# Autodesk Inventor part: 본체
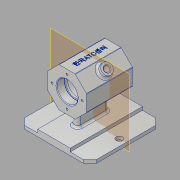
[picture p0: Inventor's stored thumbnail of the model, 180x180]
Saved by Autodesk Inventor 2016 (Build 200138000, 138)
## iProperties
Created: 2018-06
Part Number: 본체
Material: 알루미늄 6061
Document SubType Name: Modeling
Designer: 605-15
Density: 2.7 g/cm^3
Appearance: 알루미늄 - 평지
Mass: 552.644 g
Surface Area: 601.052 cm^2
Volume: 204.683 cm^3
Author: 605-15
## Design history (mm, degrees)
sketch "스케치1"
  geometry: L1 (45, 55)-(-45, 55); L2 (-55, 45)-(-55, -45); L3 (-45, -55)-(45, -55); L4 (55, -45)-(55, 45); L5 (55, 45)-(45, 55); L6 (-45, 55)-(-55, 45); L7 (-55, -45)-(-45, -55); L8 (55, -45)-(45, -55); 7 further points
  constraints: 16 end point, 8 point on line, 2 midpoint, 2 parallel, 2 perpendicular, 1 horizontal, 1 horizontal alignment, 1 vertical alignment
  dimensions: "d0" = 110 distance of point (55, -55) point (55, 55); "d1" = 10 distance of L4.end point (55, 55); "d2" = 10 distance of L1.start point (55, 55) (= d1); "d3" = 10 distance of L1.end point (-55, 55) (= d1); "d4" = 10 distance of L2.start point (-55, 55) (= d3); "d5" = 10 distance of L2.end point (-55, -55) (= d1); "d6" = 10 distance of L3.start point (-55, -55) (= d5); "d7" = 10 distance of L4.start point (55, -55) (= d1); "d8" = 10 distance of L3.end point (55, -55) (= d7)
extrude "돌출1" new body sketch "스케치1" distance "d9" = 5; taper "d10" = 0 deg
sketch "스케치2"
  geometry: L1 (-5, -19)-(-5, 19); L2 (5, 19)-(5, -19); A1 r 5 centre (0, 19) between (5, 19) and (-5, 19); A2 r 5 centre (0, -19) between (-5, -19) and (5, -19); 2 further points
  constraints: 4 end point, 4 point on circle, 4 tangent, 2 centre point, 2 vertical alignment, 1 horizontal alignment, 1 midpoint, 1 parallel, 1 vertical
  dimensions: "d11" = 38 distance of A1.centre A2.centre; "d12" = 5 radius of A2
extrude "돌출2" join sketch "스케치2" distance "d13" = 60; taper "d14" = 0 deg
sketch "스케치3"
  geometry: L1 (-12.426, 92)-(12.426, 92); L2 (12.426, 92)-(30, 74.426); L3 (30, 74.426)-(30, 49.574); L4 (30, 49.574)-(12.426, 32); L5 (12.426, 32)-(-12.426, 32); L6 (-12.426, 32)-(-30, 49.574); L7 (-30, 49.574)-(-30, 74.426); L8 (-30, 74.426)-(-12.426, 92); C1 r 30 at (0, 62); 2 further points
  constraints: 16 end point, 4 equal length, 4 tangent, 3 parallel, 2 perpendicular, 2 vertical alignment, 1 centre point, 1 horizontal, 1 midpoint
  dimensions: "d15" = 60 diameter of C1; "d16" = 45 deg dimension on C1.centre L1.end L1.start; "d17" = 62 distance of point (0, 0) C1.centre
extrude "돌출3" join sketch "스케치3" stored distance "d18" = 70; taper "d19" = 0 deg
sketch "스케치4"
  geometry: L1 (-24.853, 0)-(0, 0) reference; C1 r 8 at (-12.426, 35); 2 further points
  constraints: 1 centre point, 1 midpoint, 1 vertical alignment
  dimensions: "d20" = 16 diameter of C1; "d21" = 35 distance from line of L1 C1.centre
extrude "돌출4" join sketch "스케치4" distance "d22" = 7; taper "d23" = 0 deg
sketch "스케치5"
  geometry: L1 (92, 35)-(74.426, 35) reference; L2 (74.426, 35)-(49.574, 35) reference; L3 (49.574, 35)-(32, 35) reference; L4 (32, -35)-(49.574, -35) reference; L5 (49.574, -35)-(74.426, -35) reference; L6 (74.426, -35)-(92, -35) reference; L7 (62, 35)-(62, -35); L8 (78, 35)-(78, 23); L9 (78, 23)-(76, 23); L10 (76, 23)-(76, 20); L11 (76, 20)-(87, 20); L12 (87, 20)-(87, -20); L13 (87, -20)-(76, -20); L14 (76, -20)-(76, -23); L15 (76, -23)-(78, -23); L16 (78, -23)-(78, -35); 1 further point
  constraints: 20 end point, 6 perpendicular, 6 point on line, 2 collinear, 2 midpoint, 1 vertical
  dimensions: "d24" = 3 distance of L9.end L10.end; "d25" = 32 diameter of L8 L7; "d26" = 50 diameter of L12 L7; "d27" = 12 distance of L15.end L16.end; "d28" = 28 diameter of L14 L7
revolve "회전1" sketch "스케치5" stored, may be unused: angle "d29" = 90 deg
sketch "스케치6"
  geometry: L1 (-25, -55)-(25, -55); L2 (25, -55)-(25, 55); L3 (25, 55)-(-25, 55); L4 (-25, 55)-(-25, -55); L5 (-45, -55)-(45, -55) reference; L6 (45, 55)-(-45, 55) reference; L7 (-55, 45)-(-55, -45) reference; 3 further points
  constraints: 8 end point, 2 midpoint, 2 parallel, 1 collinear, 1 horizontal, 1 horizontal alignment, 1 perpendicular, 1 vertical alignment
  dimensions: "d31" = 30 distance between parallel lines of L4 L7
extrude "돌출5" join sketch "스케치6" distance "d32" = 5; taper "d33" = 0 deg
sketch "스케치7"
  geometry: C1 r 16 at (0, 62) reference; A1 r 23 centre (0, 62) between (0, 85) and (0, 39); 3 further points
  constraints: 4 point on circle, 2 horizontal alignment, 2 vertical alignment, 1 centre point, 1 coincident
  dimensions: "d34" = 46 diameter of A1
hole "구멍1" sketch "스케치7" at (0, 85), (0, 39), (23, 62), (-23, 62) diameter "d35" = 3.242; stored, may be unused: countersink angle "d39" = 90 deg, drill point angle "d41" = 118 deg; dims "d36" = 8, "d37" = 4, "d38" = 2, "d40" = 10
hole "구멍2" diameter "d44" = 8; stored, may be unused: countersink angle "d48" = 90 deg, drill point angle "d50" = 0 deg; dims "d42" = 10, "d43" = 10, "d45" = 8, "d46" = 4, "d47" = 2, "d49" = 15
sketch "스케치8"
  geometry: L1 (-55, 45)-(-55, -45) reference; L2 (55, -45)-(55, 45) reference; 3 further points
  constraints: 2 horizontal alignment
  dimensions: "d51" = 10 distance from line of point (-45, 0) L1; "d52" = 10 distance from line of L2 point (45, 0)
hole "구멍3" sketch "스케치8" at (-45, 0), (45, 0) diameter "d53" = 10; stored, may be unused: countersink angle "d57" = 90 deg, drill point angle "d59" = 0 deg; dims "d54" = 8, "d55" = 4, "d56" = 2, "d58" = 15
sketch "스케치9"
  geometry: 2 further points
  constraints: 1 coincident, 1 other
feature "엠보싱1" sketch "스케치9" dims "d11" = 38, "d12" = 5, "d60" = 0.5, "d61" = 0
fillet "모깎기1" dims "d62" = 0.3
fillet "모깎기2" dims "d63" = 1
fillet "모깎기3" dims "d64" = 3
chamfer "모따기1" distance "d65" = 1; stored, may be unused: second distance "d66" = 2, angle "d67" = 45 deg
node "솔리드1"
mirror "대칭1"
